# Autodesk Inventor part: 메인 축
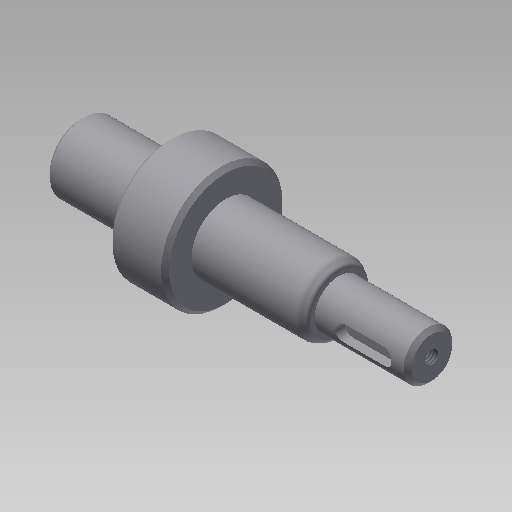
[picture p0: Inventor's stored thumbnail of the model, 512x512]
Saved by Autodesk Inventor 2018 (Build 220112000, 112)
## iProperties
Created: 2016-04
Part Number: 메인 축
Document SubType Name: Modeling
Designer: mdu
Density: 7.86 g/cm^3
Mass: 230.24 g
Surface Area: 74.3518 cm^2
Volume: 29.2926 cm^3
Material: 강철, 연강
Appearance: 금속-강(스테인리스, 브러시됨)
Author: mdu
Revision Number: 1
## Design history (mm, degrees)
sketch "스케치1"
  geometry: L1 (10.497, -57.5)-(97.497, -57.5); L2 (10.497, -66)-(32.497, -66); L3 (32.497, -72.5)-(46.5, -72.5); L4 (46.5, -66)-(74.497, -66); L5 (97.497, -63.5)-(97.497, -57.5); L6 (10.497, -66)-(10.497, -57.5); L7 (46.5, -69.749)-(46.5, -45.251) reference; L8 (46.5, -72.5)-(46.5, -66); L9 (32.497, -72.5)-(32.497, -66); L10 (32.497, -35)-(32.497, -80) reference; L11 (97.497, -63.5)-(74.497, -63.5); L12 (74.497, -63.5)-(74.497, -66); 3 further points
  constraints: 20 end point, 4 perpendicular, 3 point on line, 2 parallel, 1 collinear, 1 horizontal, 1 midpoint
  dimensions: "d0" = 17 diameter of L4 L1; "d1" = 30 diameter of L3 L1; "d2" = 22 distance of L2.start L2.end; "d5" = 17 diameter of L2 L1; "d19" = 65 distance between parallel lines of L5 L9; "d21" = 50.99692 distance between parallel lines of L5 L8 (derived); "d22" = 23 distance between parallel lines of L5 L12; "d23" = 12 diameter of L11 L1
revolve "회전1" sketch "스케치1" stored, may be unused: angle "d4" = 90 deg
chamfer "모따기1" distance "d6" = 1; stored, may be unused: second distance "d7" = 2, angle "d8" = 45 deg
node "작업 평면1"
sketch "스케치2"
  geometry: L1 (10.497, -65)-(10.497, -50) reference; L2 (16.997, -55)-(25.997, -55); L3 (25.997, -60)-(16.997, -60); A1 r 2.5 centre (25.997, -57.5) between (25.997, -60) and (25.997, -55); A2 r 2.5 centre (16.997, -57.5) between (16.997, -55) and (16.997, -60); 2 further points
  constraints: 4 end point, 4 point on circle, 4 tangent, 2 centre point, 1 horizontal alignment, 1 midpoint, 1 parallel, 1 perpendicular
  dimensions: "d9" = 5 distance between parallel lines of L3 L2; "d10" = 14 dimension on A1 A2; "d11" = 4 distance edge to line of A2 L1
extrude "돌출1" cut sketch "스케치2" distance "d12" = 3; taper "d13" = 0 deg
node "작업 평면2"
sketch "스케치3"
  geometry: L1 (91.497, -55.5)-(81.497, -55.5); L2 (81.497, -59.5)-(91.497, -59.5); L3 (97.497, -52.5)-(97.497, -62.5) reference; A1 r 2 centre (81.497, -57.5) between (81.497, -55.5) and (81.497, -59.5); A2 r 2 centre (91.497, -57.5) between (91.497, -59.5) and (91.497, -55.5); 4 further points
  constraints: 4 end point, 4 point on circle, 4 tangent, 2 centre point, 2 horizontal, 2 point on line, 1 horizontal alignment, 1 midpoint, 1 vertical alignment
  dimensions: "d32" = 14 dimension on A2 A1; "d34" = 4 distance edge to line of A2 L3; "d35" = 4 distance between parallel lines of L2 L1
extrude "돌출2" cut sketch "스케치3" distance "d16" = 2.5; taper "d17" = 0 deg
sketch "스케치4"
  geometry: L1 (74.497, -50.05)-(72.678, -49); L2 (74.497, -49)-(46.5, -49) reference; L3 (74.497, -49)-(74.497, -66) reference; L4 (74.497, -66)-(46.5, -66) reference; L5 (74.497, -57.5)-(60.711, -57.5); 1 further point
  constraints: 4 end point, 2 point on line, 1 midpoint, 1 parallel
  dimensions: "d24" = 14.9 diameter of L1.start L5; "d26" = 30 deg angle of L2 L1
revolve "회전2" sketch "스케치4" stored, may be unused: angle "d28" = 90 deg
fillet "모깎기1" dims "d29" = 1
fillet "모깎기2" dims "d30" = 2
hole "구멍1" diameter "d38" = 3.242; stored, may be unused: countersink angle "d42" = 90 deg, drill point angle "d44" = 118 deg; dims "d39" = 8, "d40" = 4, "d41" = 2, "d43" = 10, "d45" = 10, "d46" = 10
node "솔리드1"
node "참조4"
node "참조5"
other parameters: "d20" = 6, "d47" = -8.5
